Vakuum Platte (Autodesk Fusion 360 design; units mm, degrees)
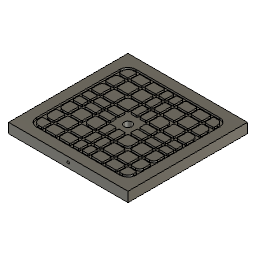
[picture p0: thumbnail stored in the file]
sketch "Skizze1" plane through (0, 0, 0) normal (0, 0, 1) x axis (1, 0, 0)
  line L1 (300, 0) -> (0, 0)
  line L2 (300, -300) -> (300, 0)
  line L3 (0, -300) -> (300, -300)
  line L4 (0, 0) -> (0, -300)
  point P1 (0, 0)
  point P2 (0, 0)
  point P3 (300, 0)
  point P5 (0, -300)
  horizontal L1
  vertical L2
  horizontal L3
  vertical L4
  coincident P1 P2
  dimension "d1" distance P2 P3 = 300
  dimension "d2" distance P2 P5 = 300
extrude "Extrusion1" new body sketch "Skizze1" along normal blind 25
sketch "Skizze2" plane through (0, 0, 25) normal (0, 0, 1) x axis (-1, 0, 0)
  line L1 (-300, 300) -> (0, 300)
  line L2 (-300, 0) -> (-300, 300)
  line L3 (0, 0) -> (-300, 0)
  line L4 (0, 300) -> (0, 0)
  line L5 (-255, 25) -> (-45, 25)
  line L6 (-275, 255) -> (-275, 45)
  line L7 (-45, 275) -> (-255, 275)
  line L8 (-25, 45) -> (-25, 255)
  line L9 (-170, 130) -> (-130, 130)
  line L10 (-170, 170) -> (-170, 130)
  line L11 (-130, 170) -> (-170, 170)
  line L12 (-130, 130) -> (-130, 170)
  line L13 (-31, 46124) -> (-130, 46124)
  line L14 (-269, 46124) -> (-170, 46124)
  line L15 (-170, 46124) -> (-130, 46124)
  line L16 (-269, 46130) -> (-170, 46130)
  line L17 (-170, 46130) -> (-130, 46130)
  line L18 (-31, 46130) -> (-130, 46130)
  line L19 (-170, 170) -> (-130, 170)
  line L20 (-52, 31) -> (-45, 31)
  line L21 (-87, 31) -> (-62, 31)
  line L22 (-122, 31) -> (-97, 31)
  line L23 (-168, 31) -> (-155, 31)
  line L24 (-203, 31) -> (-178, 31)
  line L25 (-238, 31) -> (-213, 31)
  line L26 (-255, 31) -> (-248, 31)
  line L27 (-31, 45) -> (-31, 52)
  line L28 (-31, 70) -> (-31, 87)
  line L29 (-31, 105) -> (-31, 122)
  line L30 (-31, 178) -> (-31, 195)
  line L31 (-31, 248) -> (-31, 255)
  line L32 (-31, 213) -> (-31, 230)
  line L33 (-45, 269) -> (-52, 269)
  line L34 (-62, 269) -> (-87, 269)
  line L35 (-97, 269) -> (-122, 269)
  line L36 (-178, 269) -> (-203, 269)
  line L37 (-41, 205) -> (-52, 205)
  line L38 (-33, 211) -> (-52, 211)
  line L39 (-105, 205) -> (-122, 205)
  line L40 (-62, 205) -> (-87, 205)
  line L41 (-97, 211) -> (-122, 211)
  line L42 (-62, 211) -> (-87, 211)
  line L43 (-54, 267) -> (-54, 248)
  line L44 (-60, 248) -> (-60, 267)
  line L45 (-89, 267) -> (-89, 248)
  line L46 (-95, 248) -> (-95, 267)
  line L47 (-124, 267) -> (-124, 248)
  line L48 (-130, 248) -> (-130, 267)
  line L49 (-97, 246) -> (-122, 246)
  line L50 (-62, 246) -> (-87, 246)
  line L51 (-33, 246) -> (-52, 246)
  line L52 (-170, 248) -> (-170, 267)
  line L53 (-176, 267) -> (-176, 248)
  line L54 (-124, 238) -> (-124, 213)
  line L55 (-95, 213) -> (-95, 238)
  line L56 (-89, 238) -> (-89, 213)
  line L57 (-60, 213) -> (-60, 238)
  line L58 (-54, 238) -> (-54, 213)
  line L59 (-130, 213) -> (-130, 238)
  line L60 (-170, 213) -> (-170, 238)
  line L61 (-176, 238) -> (-176, 213)
  line L62 (-267, 211) -> (-248, 211)
  line L63 (-203, 211) -> (-178, 211)
  line L64 (-238, 211) -> (-213, 211)
  line L65 (-203, 240) -> (-178, 240)
  line L66 (-238, 240) -> (-213, 240)
  line L67 (-259, 240) -> (-248, 240)
  line L68 (-269, 230) -> (-269, 213)
  line L69 (-269, 255) -> (-269, 248)
  line L70 (-246, 238) -> (-246, 213)
  line L71 (-246, 267) -> (-246, 248)
  line L72 (-267, 246) -> (-248, 246)
  line L73 (-240, 248) -> (-240, 267)
  line L74 (-240, 213) -> (-240, 238)
  line L75 (-248, 269) -> (-255, 269)
  line L76 (-213, 269) -> (-238, 269)
  line L77 (-203, 246) -> (-178, 246)
  line L78 (-238, 246) -> (-213, 246)
  line L79 (-211, 238) -> (-211, 213)
  line L80 (-211, 267) -> (-211, 248)
  line L81 (-205, 248) -> (-205, 267)
  line L82 (-205, 213) -> (-205, 238)
  line L83 (-97, 176) -> (-122, 176)
  line L84 (-97, 170) -> (-122, 170)
  line L85 (-62, 170) -> (-87, 170)
  line L86 (-33, 170) -> (-52, 170)
  line L87 (-62, 176) -> (-87, 176)
  line L88 (-33, 176) -> (-52, 176)
  line L89 (-54, 203) -> (-54, 178)
  line L90 (-60, 178) -> (-60, 203)
  line L91 (-89, 203) -> (-89, 178)
  line L92 (-95, 178) -> (-95, 195)
  line L93 (-124, 203) -> (-124, 178)
  line L94 (-130, 178) -> (-130, 203)
  line L95 (-170, 178) -> (-170, 203)
  line L96 (-176, 203) -> (-176, 178)
  line L97 (-205, 178) -> (-205, 195)
  line L98 (-211, 203) -> (-211, 178)
  line L99 (-240, 178) -> (-240, 203)
  line L100 (-246, 203) -> (-246, 178)
  line L101 (-269, 195) -> (-269, 178)
  line L102 (-267, 170) -> (-248, 170)
  line L103 (-267, 176) -> (-248, 176)
  line L104 (-203, 170) -> (-178, 170)
  line L105 (-238, 170) -> (-213, 170)
  line L106 (-203, 176) -> (-178, 176)
  line L107 (-238, 176) -> (-213, 176)
  line L108 (-267, 130) -> (-248, 130)
  line L109 (-238, 130) -> (-213, 130)
  line L110 (-267, 124) -> (-248, 124)
  line L111 (-203, 124) -> (-178, 124)
  line L112 (-238, 124) -> (-213, 124)
  line L113 (-170, 130) -> (-170, 170)
  line L114 (-130, 130) -> (-130, 170)
  line L115 (-97, 124) -> (-122, 124)
  line L116 (-97, 130) -> (-122, 130)
  line L117 (-62, 124) -> (-87, 124)
  line L118 (-33, 124) -> (-52, 124)
  line L119 (-62, 130) -> (-87, 130)
  line L120 (-33, 130) -> (-52, 130)
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  point P46 (-170, 31)
  point P52 (-150, 0)
  point P47 (-176, 31)
  point P290 (-205, 203)
  point P251 (-95, 203)
  point P252 (-97, 205)
  point P48 (-205, 31)
  point P49 (-211, 31)
  point P50 (-246, 31)
  point P51 (-240, 31)
  horizontal L5
  vertical L6
  horizontal L7
  vertical L8
  horizontal L9
  vertical L10
  horizontal L11
  vertical L12
  perpendicular L31 L116
  horizontal L17
  vertical L52
  coincident P46 L20
  vertical L81
  vertical L73
  collinear L20 L21
  collinear L21 L22
  collinear L22 L23
  collinear L23 L24
  collinear L24 L25
  collinear L25 L26
  collinear L27 L31
  collinear L28 L31
  collinear L29 L31
  collinear L30 L31
  collinear L31 L32
  collinear L33 L75
  collinear L34 L75
  collinear L35 L75
  collinear L36 L75
  collinear L37 L39
  collinear L38 L41
  collinear L39 L40
  collinear L41 L42
  collinear L44 L57
  collinear L46 L55
  collinear L48 L59
  collinear L49 L50
  collinear L50 L51
  collinear L52 L60
  collinear L55 L92
  collinear L57 L90
  collinear L59 L94
  collinear L60 L95
  collinear L81 L97
  collinear L73 L99
  collinear L62 L63
  collinear L63 L64
  collinear L65 L66
  collinear L66 L67
  collinear L68 L69
  collinear L70 L71
  collinear L72 L77
  collinear L73 L74
  collinear L75 L76
  collinear L77 L78
  collinear L79 L80
  collinear L81 L82
  collinear L83 L87
  collinear L84 L85
  collinear L85 L86
  collinear L87 L88
  collinear L94 L114
  collinear L95 L113
  collinear L102 L104
  collinear L103 L106
  collinear L104 L105
  collinear L106 L107
  collinear L110 L111
  collinear L111 L112
  collinear L115 L117
  collinear L116 L119
  collinear L117 L118
  collinear L119 L120
  coincident L3 P52
  coincident P47 L24
  coincident L97 P290
  coincident L92 P251
  coincident L39 P252
  dimension "d5" radius = 20
  dimension "d9" diameter = 20
  dimension "d11" = -6
  dimension "d15" distance P46 P47 = 6
  dimension "d16" distance P48 P49 = 6
  dimension "d17" distance P50 P51 = 6
  dimension "d22" radius = 10
  dimension "d23" radius = 10
  dimension "d24" radius = 10
  dimension "d25" radius = 2
  dimension "d26" radius = 2
  dimension "d27" radius = 2
  dimension "d28" radius = 2
  dimension "d29" radius = 2
  dimension "d30" radius = 2
  dimension "d31" radius = 2
  dimension "d40" radius = 10
  dimension "d41" radius = 10
  dimension "d42" radius = 10
extrude "Extrusion2" cut sketch "Skizze2" against normal blind 20
extrude "Extrusion3" cut sketch "Skizze2" against normal blind 4.5
extrude "Extrusion4" cut sketch "Skizze2" against normal blind 10
extrude "Extrusion5" add of existing geometry blind 5.5
sketch "Skizze3" plane through (0, -300, 0) normal (0, -1, 0) x axis (1, 0, 0)
  line L1 (300, 0) -> (0, 0)
  line L2 (300, 25) -> (300, 0)
  line L3 (0, 25) -> (300, 25)
  line L4 (0, 0) -> (0, 25)
  circle C1 centre (150, 12.5) radius 3
  dimension "d43" diameter C1 = 6
extrude "Extrusion6" cut sketch "Skizze3" profile of C1 against normal blind 148.767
